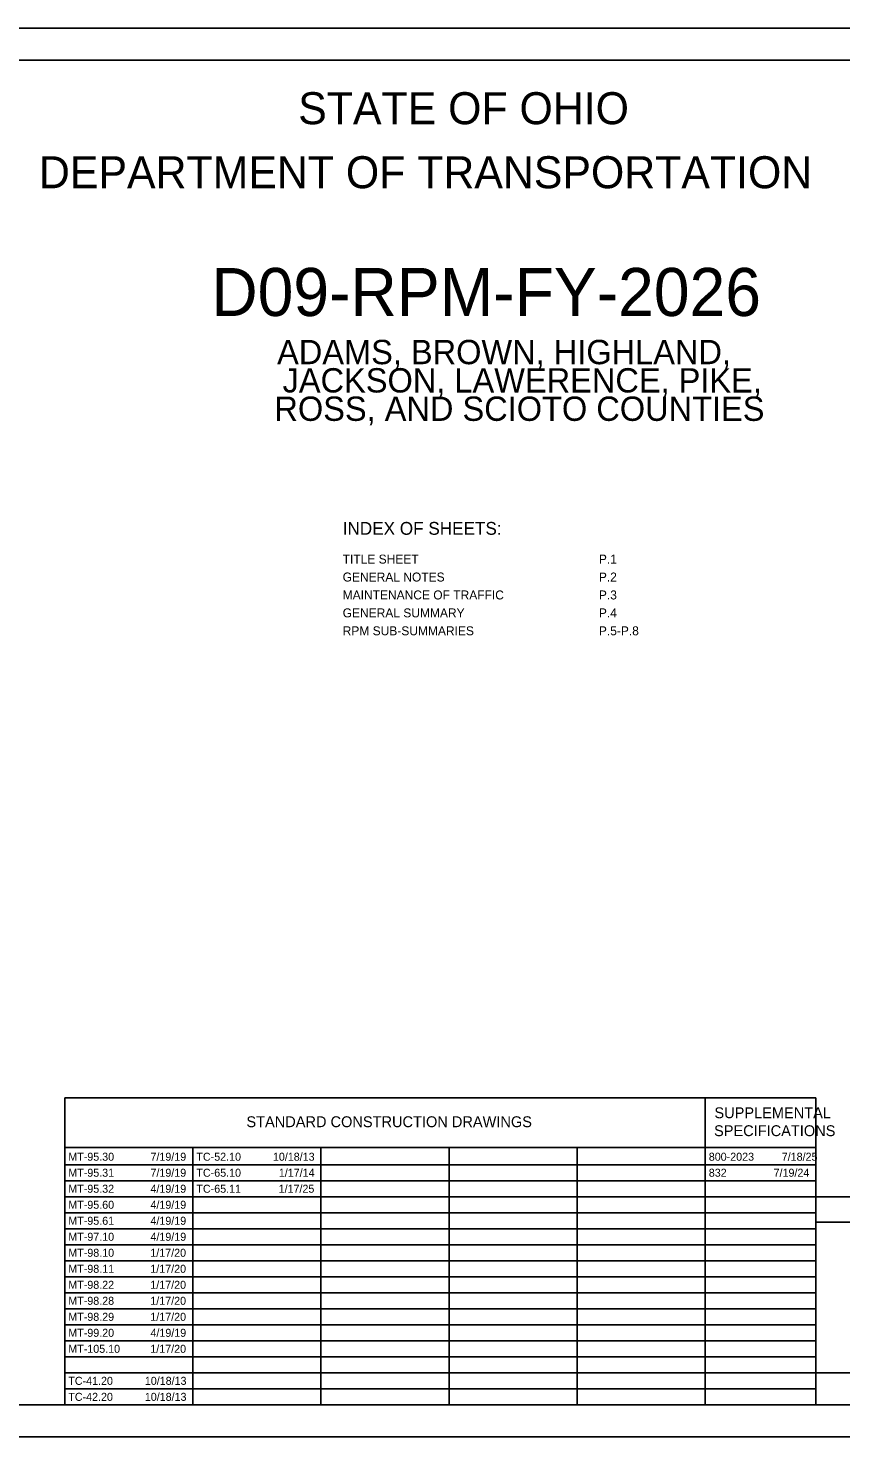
# Model space of a CAD drawing. Extents: x 0 to 34, y 0 to 22.
# Drawn here: x 9.58 to 22.27, y 0 to 22 of the extents above; entities that cross this region are included whole.
import ezdxf

# ---------------------------------------------------------------- set-up
doc = ezdxf.new("R2010")
doc.units = 0
for name, color, linetype in [('Default', 7, 'Continuous'), ('SH_Border', 7, 'Continuous'), ('SH_Cut_Line', 7, 'Continuous'), ('SH_Data', 7, 'Continuous'), ('SH_Text', 7, 'Continuous')]:
    doc.layers.add(name, color=color, linetype=linetype)

msp = doc.modelspace()

# ---------------------------------------------------------------- linework, layer by layer
at = {"layer": 'SH_Border'}
msp.add_lwpolyline([(1.5, 21.5), (33.5, 21.5), (33.5, 0.5), (1.5, 0.5)], close=True, dxfattribs=at)
at = {"layer": 'SH_Cut_Line'}
msp.add_lwpolyline([(0, 0), (34, 0), (34, 22), (0, 22)], close=True, dxfattribs=at)
at = {"layer": 'SH_Data'}
for p, q in [((10.15, 5.292), (21.875, 5.292)), ((10.15, 0.5), (10.15, 5.292)), ((20.15, 0.5), (20.15, 5.292)), ((21.875, 0.5), (21.875, 5.292)), ((10.15, 4.521), (21.875, 4.521)), ((12.15, 0.5), (12.15, 4.521)), ((14.15, 0.5), (14.15, 4.521)), ((16.15, 0.5), (16.15, 4.521)), ((18.15, 0.5), (18.15, 4.521)), ((10.15, 4.25), (21.875, 4.25)), ((10.15, 4), (21.875, 4)), ((10.15, 3.75), (21.875, 3.75)), ((21.875, 0.5), (21.875, 3.75)), ((21.875, 3.75), (24.675, 3.75)), ((10.15, 3.5), (21.875, 3.5)), ((21.875, 3.35), (24.675, 3.35)), ((10.15, 3.25), (21.875, 3.25)), ((10.15, 3), (21.875, 3)), ((10.15, 2.75), (21.875, 2.75)), ((10.15, 2.5), (21.875, 2.5)), ((10.15, 2.25), (21.875, 2.25)), ((10.15, 2), (21.875, 2)), ((10.15, 1.75), (21.875, 1.75)), ((10.15, 1.5), (21.875, 1.5)), ((10.15, 1.25), (21.875, 1.25)), ((10.15, 1), (21.875, 1)), ((10.15, 0.75), (21.875, 0.75)), ((21.875, 0.5), (24.675, 0.5))]:
    msp.add_line(p, q, dxfattribs=at)
msp.add_lwpolyline([(21.875, 0.5), (21.875, 1), (24.675, 1), (24.675, 0.5)], close=True, dxfattribs=at)

# ---------------------------------------------------------------- texts
at = {"layer": 'Default'}
for s, p in [('MT-95.30', (10.205, 4.312)), ('7/19/19', (11.488, 4.312)), ('TC-52.10', (12.205, 4.312)), ('10/18/13', (13.4, 4.312)), ('800-2023', (20.205, 4.312)), ('7/18/25', (21.344, 4.312)), ('MT-95.31', (10.205, 4.062)), ('7/19/19', (11.488, 4.062)), ('TC-65.10', (12.205, 4.062)), ('1/17/14', (13.492, 4.062)), ('832', (20.205, 4.062)), ('7/19/24', (21.217, 4.062)), ('MT-95.32', (10.205, 3.812)), ('4/19/19', (11.488, 3.812)), ('TC-65.11', (12.205, 3.812)), ('1/17/25', (13.489, 3.812)), ('MT-95.60', (10.205, 3.562)), ('4/19/19', (11.488, 3.562)), ('MT-95.61', (10.205, 3.312)), ('4/19/19', (11.488, 3.312)), ('MT-97.10', (10.205, 3.062)), ('4/19/19', (11.488, 3.062)), ('MT-98.10', (10.205, 2.812)), ('1/17/20', (11.486, 2.812)), ('MT-98.11', (10.205, 2.562)), ('1/17/20', (11.486, 2.562)), ('MT-98.22', (10.205, 2.312)), ('1/17/20', (11.486, 2.312)), ('MT-98.28', (10.205, 2.062)), ('1/17/20', (11.486, 2.062)), ('MT-98.29', (10.205, 1.812)), ('1/17/20', (11.486, 1.812)), ('MT-99.20', (10.205, 1.562)), ('4/19/19', (11.488, 1.562)), ('MT-105.10', (10.205, 1.312)), ('1/17/20', (11.486, 1.312)), ('TC-41.20', (10.205, 0.812)), ('10/18/13', (11.4, 0.812)), ('TC-42.20', (10.205, 0.562)), ('10/18/13', (11.4, 0.562))]:
    msp.add_text(s, height=0.125, dxfattribs=at).set_placement(p)
at = {"layer": 'SH_Text'}
for s, height, p in [('STATE OF OHIO', 0.5, (13.795, 20.5)), ('DEPARTMENT OF TRANSPORTATION', 0.5, (9.747, 19.5)), ('D09-RPM-FY-2026', 0.75, (12.437, 17.505)), ('ADAMS, BROWN, HIGHLAND,', 0.38, (13.465, 16.752)), ('JACKSON, LAWERENCE, PIKE,', 0.38, (13.551, 16.31)), ('ROSS, AND SCIOTO COUNTIES', 0.38, (13.423, 15.867)), ('INDEX OF SHEETS:', 0.2, (14.489, 14.088)), ('TITLE SHEET', 0.14, (14.489, 13.638)), ('P.1', 0.14, (18.489, 13.638)), ('GENERAL NOTES', 0.14, (14.489, 13.358)), ('P.2', 0.14, (18.489, 13.358)), ('MAINTENANCE OF TRAFFIC', 0.14, (14.489, 13.078)), ('P.3', 0.14, (18.489, 13.078)), ('GENERAL SUMMARY', 0.14, (14.489, 12.798)), ('P.4', 0.14, (18.489, 12.798)), ('RPM SUB-SUMMARIES', 0.14, (14.489, 12.518)), ('P.5-P.8', 0.14, (18.489, 12.518)), ('SUPPLEMENTAL', 0.17, (20.293, 4.976)), ('STANDARD CONSTRUCTION DRAWINGS', 0.17, (12.986, 4.836)), ('SPECIFICATIONS', 0.17, (20.287, 4.696))]:
    msp.add_text(s, height=height, dxfattribs=at).set_placement(p)

doc.saveas('drawing.dxf')
